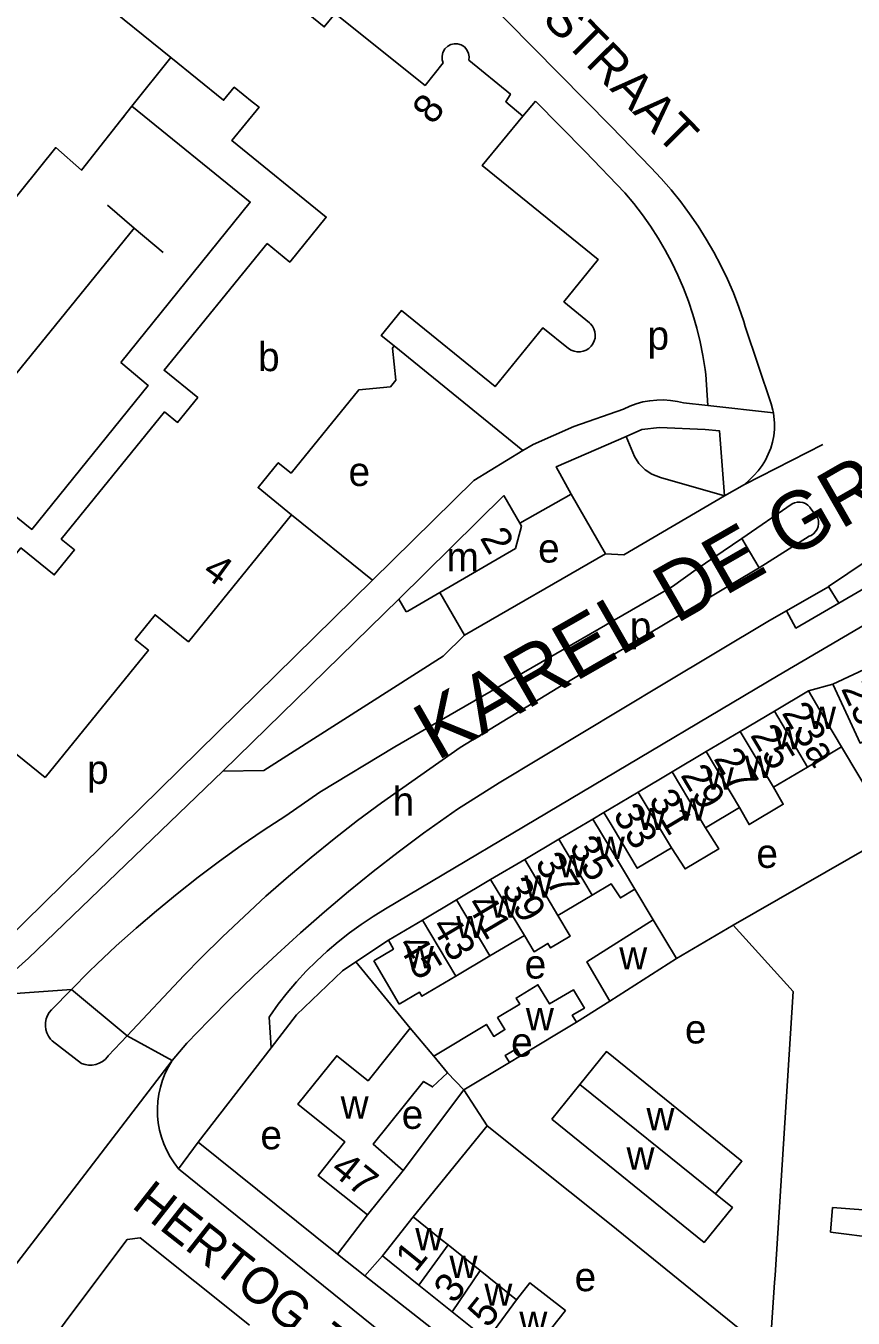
# Model space of a CAD drawing. Extents: x 159700 to 161346, y 381730 to 382922.
# Drawn here: x 160419.2 to 160533.4, y 382582.1 to 382760.5 of the extents above; entities that cross this region are included whole.
import ezdxf

# ---------------------------------------------------------------- set-up
doc = ezdxf.new("R2010")
doc.units = 0
for name, color, linetype in [('BLT_Basislijn', 7, 'Continuous'), ('BLT_Bebouwing', 7, 'Continuous'), ('BLT_Centroide', 7, 'Continuous'), ('BLT_Huisnummer', 7, 'Continuous'), ('BLT_Huisnummer_ tussenligend', 7, 'Continuous'), ('BLT_Onderverdeling_panden', 7, 'Continuous'), ('BLT_Straatnaam', 7, 'Continuous'), ('BLT_Straatnaam_hoofdweg', 7, 'Continuous'), ('BLT_Vlakafsluiter', 7, 'Continuous')]:
    doc.layers.add(name, color=color, linetype=linetype)

msp = doc.modelspace()

# ---------------------------------------------------------------- linework, layer by layer
at = {"layer": 'BLT_Basislijn'}
for p, q in [((160433.88, 382749.39), (160439.23, 382756.14)), ((160487.81, 382748.05), (160489.54, 382750.11)), ((160432.79, 382748.01), (160432.4, 382747.51)), ((160430.48, 382735.74), (160434.18, 382732.58)), ((160394.2, 382683.31), (160434.18, 382732.58)), ((160434.18, 382732.58), (160438.16, 382729.19)), ((160522.09, 382708.31), (160518.51, 382719)), ((160470.04, 382716.3), (160487.83, 382701.85)), ((160513.04, 382712.36), (160513.32, 382708.08)), ((160509.97, 382708.45), (160513.32, 382708.08)), ((160513.32, 382708.08), (160522.38, 382707.07)), ((160501.71, 382707.58), (160494.84, 382705.19)), ((160494.48, 382695.83), (160499.22, 382687.59)), ((160518.38, 382697.17), (160515.63, 382695.63)), ((160524.97, 382694.49), (160518.01, 382689.74)), ((160527.46, 382693.97), (160528.5, 382692.53)), ((160455.9, 382693.01), (160467.05, 382683.96)), ((160518.01, 382689.74), (160520.41, 382685.67)), ((160520.41, 382685.67), (160527.33, 382690.04)), ((160529.99, 382683.09), (160531.4, 382680.79)), ((160476.35, 382682.26), (160479.74, 382676.38)), ((160530.58, 382669.62), (160527.22, 382668.68)), ((160531.8, 382660.96), (160536.7, 382652.73)), ((160478.8, 382652.34), (160474.12, 382649.06)), ((160499.01, 382651.92), (160497.47, 382650.99)), ((160505.79, 382637.1), (160503.26, 382641.3)), ((160509.03, 382631.73), (160516.84, 382636.33)), ((160464.76, 382631.29), (160469.26, 382634.26)), ((160472.26, 382622.14), (160464.76, 382631.29)), ((160427.97, 382629.95), (160425.54, 382627.48)), ((160441.06, 382629.42), (160433.23, 382621.08)), ((160425.54, 382627.48), (160422.77, 382624.66)), ((160425.54, 382627.48), (160433.23, 382621.08)), ((160495.21, 382622.93), (160499.8, 382625.87)), ((160452.79, 382623.66), (160453.08, 382619.43)), ((160433.23, 382621.08), (160430.61, 382618.29)), ((160426.93, 382617.24), (160422.87, 382620.39)), ((160453.08, 382619.43), (160443.02, 382606.37)), ((160485.97, 382617.39), (160487.51, 382618.29)), ((160479.66, 382613.62), (160471.31, 382602.49)), ((160482.89, 382608.65), (160479.66, 382613.62)), ((160482.89, 382608.65), (160472.7, 382596.06)), ((160440.32, 382602.72), (160443.02, 382606.37)), ((160466.4, 382596.34), (160462.26, 382590.93)), ((160466, 382587.92), (160462.26, 382590.93)), ((160466, 382587.92), (160468.44, 382590.7)), ((160521.9, 382577.2), (160522.55, 382587.01))]:
    msp.add_line(p, q, dxfattribs=at)
for points in [[(160505.49, 382740.93), (160500, 382746.62), (160428.28, 382819.33), (160426.69, 382820.38), (160424.21, 382820.93), (160420.96, 382820.92), (160420.04, 382820.56)], [(160392.93, 382705.85), (160423.37, 382743.68), (160426.9, 382740.56), (160433.88, 382749.39)], [(160433.88, 382749.39), (160450.2, 382736.17), (160432.34, 382714)], [(160501.9, 382737.46), (160496.42, 382743.13), (160489.54, 382750.11)], [(160505.49, 382740.93), (160506.92, 382739.41), (160508.29, 382737.84), (160509.59, 382736.22), (160510.83, 382734.54), (160512.01, 382732.82), (160513.12, 382731.06), (160514.16, 382729.25), (160515.13, 382727.41), (160516.03, 382725.53), (160516.86, 382723.62), (160517.62, 382721.67), (160518.29, 382719.7), (160518.51, 382719)], [(160501.9, 382737.46), (160503.14, 382735.97), (160504.31, 382734.43), (160505.43, 382732.84), (160506.47, 382731.2), (160507.45, 382729.53), (160508.36, 382727.82), (160509.2, 382726.06), (160509.96, 382724.28), (160510.65, 382722.47), (160511.27, 382720.63), (160511.81, 382718.76), (160512.27, 382716.88), (160512.65, 382714.98), (160512.95, 382713.06), (160513.04, 382712.36)], [(160390.87, 382673.81), (160393.15, 382674.12), (160397.54, 382670.63), (160416.19, 382694.1), (160420.05, 382690.98), (160436.13, 382710.83), (160432.34, 382714)], [(160501.71, 382707.58), (160502.57, 382707.98), (160503.47, 382708.31), (160504.39, 382708.57), (160505.33, 382708.74), (160506.28, 382708.84), (160507.23, 382708.85), (160508.19, 382708.79), (160509.13, 382708.65), (160509.97, 382708.45)], [(160522.09, 382708.31), (160522.32, 382707.45), (160522.38, 382707.07)], [(160522.38, 382707.07), (160522.46, 382706.57), (160522.53, 382705.68), (160522.52, 382704.79), (160522.43, 382703.91), (160522.26, 382703.03), (160522.01, 382702.18), (160521.68, 382701.35), (160521.29, 382700.55), (160520.82, 382699.79), (160520.29, 382699.07), (160519.69, 382698.41), (160519.04, 382697.8), (160518.38, 382697.17)], [(160494.84, 382705.19), (160489.24, 382702.71), (160487.83, 382701.85)], [(160502.06, 382703.81), (160504.23, 382704.75), (160506.67, 382705.06), (160512.96, 382704.75), (160514.93, 382704.59), (160515.63, 382695.63)], [(160494.48, 382695.83), (160492.42, 382699.63), (160502.06, 382703.81)], [(160515.63, 382695.63), (160506.82, 382698.15), (160505.6, 382698.61), (160504.71, 382699.21), (160503.82, 382700.1), (160503.2, 382701.04), (160502.06, 382703.81)], [(160487.83, 382701.85), (160481.07, 382697.74), (160467.05, 382683.96)], [(160529.99, 382683.09), (160548.53, 382695.55), (160552.09, 382697.77)], [(160494.48, 382695.83), (160487.4, 382691.84)], [(160515.63, 382695.63), (160501.75, 382687.49), (160499.22, 382687.59)], [(160524.97, 382694.49), (160525.32, 382694.66), (160525.69, 382694.75), (160526.07, 382694.76), (160526.45, 382694.7), (160526.81, 382694.55), (160527.12, 382694.34), (160527.39, 382694.06), (160527.46, 382693.97)], [(160531.4, 382680.79), (160541.2, 382686.51), (160551.14, 382692.14), (160554.4, 382693.75)], [(160528.5, 382692.53), (160528.6, 382692.15), (160528.61, 382691.75), (160528.55, 382691.36), (160528.41, 382691), (160528.19, 382690.67), (160527.92, 382690.38), (160527.59, 382690.16), (160527.33, 382690.04)], [(160518.01, 382689.74), (160511.75, 382685.46), (160508.48, 382683.1), (160475.37, 382663.99), (160470.14, 382660.98), (160459.8, 382654.69), (160455.09, 382651.42)], [(160555.31, 382689.89), (160546.62, 382684.68), (160523.06, 382670.8), (160468.88, 382638.59)], [(160479.74, 382676.38), (160499.22, 382687.59)], [(160468.31, 382653.25), (160479.17, 382660.85), (160492.65, 382669.09), (160519.87, 382685.33), (160520.41, 382685.67)], [(160467.05, 382683.96), (160419.05, 382636.78), (160417.13, 382634.83)], [(160524.19, 382679.74), (160529.88, 382683.01), (160529.99, 382683.09)], [(160470.7, 382681.36), (160446.43, 382657.59)], [(160507.17, 382669.62), (160521.83, 382678.39), (160524.19, 382679.74)], [(160524.19, 382679.74), (160525.49, 382677.35), (160531.4, 382680.79)], [(160446.43, 382657.59), (160452.08, 382657.71), (160476.8, 382673.46), (160479.74, 382676.38)], [(160507.17, 382669.62), (160484.56, 382656), (160478.8, 382652.34)], [(160446.43, 382657.59), (160419.61, 382631.81), (160413.81, 382626.64)], [(160468.31, 382653.25), (160465.02, 382650.79), (160461.78, 382648.27), (160458.59, 382645.68), (160455.46, 382643.04), (160452.37, 382640.33), (160449.34, 382637.56), (160446.36, 382634.74), (160443.44, 382631.85), (160441.06, 382629.42)], [(160516.84, 382636.33), (160539.04, 382649.09), (160536.7, 382652.73)], [(160455.09, 382651.42), (160452, 382649.4), (160448.96, 382647.32), (160445.96, 382645.17), (160443.01, 382642.95), (160440.11, 382640.67), (160437.25, 382638.33), (160434.45, 382635.93), (160431.71, 382633.47), (160429.01, 382630.95), (160427.97, 382629.95)], [(160474.12, 382649.06), (160470.62, 382646.43), (160467.17, 382643.74), (160463.77, 382640.99), (160460.43, 382638.17), (160457.13, 382635.3), (160453.89, 382632.36), (160450.7, 382629.36), (160447.57, 382626.31), (160444.49, 382623.2), (160441.47, 382620.04), (160439.42, 382617.66)], [(160468.88, 382638.59), (160467.18, 382637.55), (160465.51, 382636.45), (160463.89, 382635.28), (160462.32, 382634.05), (160460.8, 382632.75), (160459.34, 382631.39), (160457.93, 382629.98), (160456.57, 382628.51), (160455.28, 382626.99), (160454.05, 382625.42), (160452.88, 382623.8), (160452.79, 382623.66)], [(160516.84, 382636.33), (160525.13, 382627.17), (160522.63, 382588.01), (160522.55, 382587.01)], [(160464.76, 382631.29), (160462.91, 382630.06), (160456.58, 382623.97), (160453.08, 382619.43)], [(160422.77, 382624.66), (160422.46, 382624.28), (160422.22, 382623.85), (160422.05, 382623.39), (160421.95, 382622.91), (160421.94, 382622.42), (160422, 382621.93), (160422.15, 382621.46), (160422.36, 382621.02), (160422.65, 382620.62), (160422.87, 382620.39)], [(160426.93, 382617.24), (160427.4, 382617.09), (160427.89, 382617.02), (160428.39, 382617.03), (160428.88, 382617.11), (160429.35, 382617.28), (160429.79, 382617.51), (160430.18, 382617.81), (160430.52, 382618.18), (160430.61, 382618.29)], [(160440.32, 382602.72), (160439.71, 382603.51), (160439.16, 382604.35), (160438.68, 382605.23), (160438.27, 382606.15), (160437.94, 382607.09), (160437.69, 382608.06), (160437.51, 382609.04), (160437.41, 382610.04), (160437.39, 382611.04), (160437.45, 382612.04), (160437.59, 382613.03), (160437.81, 382614), (160438.11, 382614.96), (160438.48, 382615.89), (160438.93, 382616.79), (160439.42, 382617.66)], [(160482.89, 382608.65), (160500, 382594.99), (160521.9, 382577.2)], [(160462.26, 382590.93), (160461.96, 382591.17), (160443.02, 382606.37)], [(160491.46, 382544.8), (160497.56, 382552.05), (160497.99, 382554.89), (160497.77, 382555.53), (160491.25, 382561.57), (160440.32, 382602.72)], [(160425.28, 382599.18), (160384.45, 382546.02), (160383.14, 382544.19), (160379.74, 382536.86), (160366.91, 382518.26), (160360.11, 382511.98), (160356.18, 382508.31), (160321.11, 382459.87)], [(160450.08, 382581.13), (160435.03, 382593.18), (160433.21, 382592.93), (160424.89, 382581.85), (160387.63, 382530.18), (160388, 382528.33), (160391.85, 382526)], [(160506.02, 382557.47), (160500, 382561.24), (160466, 382587.92)]]:
    msp.add_lwpolyline(points, dxfattribs=at)
at = {"layer": 'BLT_Bebouwing'}
for p, q in [((160485.19, 382695.64), (160487.4, 382691.84)), ((160487.65, 382691.41), (160486.81, 382688.34)), ((160487.4, 382691.84), (160487.65, 382691.41)), ((160486.81, 382688.34), (160476.35, 382682.26)), ((160471.73, 382679.61), (160470.7, 382681.36)), ((160476.35, 382682.26), (160471.96, 382679.7)), ((160471.96, 382679.7), (160471.73, 382679.61)), ((160535.62, 382671.95), (160530.58, 382669.62)), ((160522.52, 382665.89), (160527.22, 382668.68)), ((160517.82, 382663.09), (160522.52, 382665.89)), ((160513.12, 382660.3), (160517.82, 382663.09)), ((160508.43, 382657.51), (160513.12, 382660.3)), ((160531.8, 382660.96), (160527.11, 382658.17)), ((160527.11, 382658.17), (160522.41, 382655.38)), ((160503.73, 382654.72), (160508.43, 382657.51)), ((160517.71, 382652.59), (160513.01, 382649.8)), ((160492.77, 382648.21), (160488.07, 382645.42)), ((160488.07, 382645.42), (160483.37, 382642.63)), ((160483.37, 382642.63), (160478.66, 382639.84)), ((160497.36, 382640.47), (160492.66, 382637.68)), ((160478.66, 382639.84), (160473.96, 382637.05)), ((160473.96, 382637.05), (160469.26, 382634.26)), ((160488.02, 382634.92), (160483.26, 382632.09)), ((160483.26, 382632.09), (160478.56, 382629.3)), ((160495.21, 382622.93), (160487.51, 382618.29)), ((160472.26, 382622.14), (160475.51, 382618.24)), ((160475.51, 382618.24), (160477.43, 382615.94)), ((160485.97, 382617.39), (160479.66, 382613.62)), ((160495.69, 382614.36), (160491.82, 382609.55)), ((160471.31, 382602.49), (160466.4, 382596.34)), ((160468.44, 382590.7), (160472.7, 382596.06)), ((160477.5, 382592.2), (160481.91, 382588.65)), ((160473.46, 382586.66), (160468.44, 382590.7)), ((160481.91, 382588.65), (160486.92, 382584.62)), ((160478.08, 382582.95), (160473.46, 382586.66)), ((160482.88, 382579.09), (160478.08, 382582.95))]:
    msp.add_line(p, q, dxfattribs=at)
for points in [[(160471.4, 382754.61), (160461.91, 382762.21), (160460.41, 382760.36), (160456.95, 382763.17), (160460.66, 382767.73)], [(160428.99, 382764.45), (160439.23, 382756.14)], [(160476.84, 382755.38), (160476.7, 382755.81), (160476.68, 382756.32), (160476.79, 382756.84), (160477.06, 382757.31), (160477.45, 382757.68), (160477.89, 382757.92), (160478.34, 382758.02), (160478.8, 382758.02), (160479.28, 382757.88), (160479.74, 382757.6), (160480.1, 382757.19), (160480.33, 382756.7), (160480.41, 382756.21), (160480.36, 382755.75)], [(160439.23, 382756.14), (160446.52, 382750.22), (160447.98, 382752.03), (160450.48, 382750), (160451.41, 382749.25), (160447.68, 382744.66), (160460.69, 382734.09), (160455.66, 382727.89), (160452.52, 382730.44)], [(160476.84, 382755.38), (160474.32, 382752.27), (160471.4, 382754.61)], [(160487.81, 382748.05), (160485.45, 382750.02), (160486.09, 382751.07), (160480.36, 382755.75)], [(160497.01, 382719.52), (160493.47, 382722.4), (160498.21, 382728.23), (160482.22, 382741.21), (160487.81, 382748.05)], [(160404.37, 382670.95), (160418.56, 382688.43), (160423.15, 382684.7), (160425.96, 382688.15), (160424.12, 382689.64), (160438.38, 382707.2), (160440.17, 382705.75), (160442.95, 382709.18), (160438.31, 382712.94), (160452.52, 382730.44)], [(160494.12, 382715.95), (160490.59, 382718.82), (160483.99, 382710.7), (160471.05, 382721.2), (160468.25, 382717.76), (160470.04, 382716.3)], [(160494.12, 382715.95), (160494.48, 382715.72), (160494.88, 382715.57), (160495.3, 382715.49), (160495.73, 382715.49), (160496.15, 382715.58), (160496.55, 382715.73), (160496.91, 382715.96), (160497.23, 382716.26), (160497.48, 382716.6), (160497.66, 382716.99), (160497.77, 382717.4), (160497.8, 382717.83), (160497.75, 382718.26), (160497.63, 382718.66), (160497.43, 382719.04), (160497.16, 382719.38), (160497.01, 382719.52)], [(160470.04, 382716.3), (160469.81, 382716.02), (160470.27, 382711.59), (160469.53, 382710.68), (160465.16, 382710.23), (160455.84, 382698.75), (160454.07, 382700.19), (160451.29, 382696.76), (160455.9, 382693.01)], [(160470.7, 382681.36), (160485.19, 382695.64)], [(160455.9, 382693.01), (160441.66, 382675.48), (160437.07, 382679.2), (160434.3, 382675.8), (160436.15, 382674.3), (160421.88, 382656.73)], [(160530.58, 382669.62), (160532.68, 382665.08), (160534.35, 382661.48), (160539.39, 382663.82)], [(160527.22, 382668.68), (160529.77, 382664.38), (160531.8, 382660.96)], [(160421.88, 382656.73), (160416.09, 382661.44), (160413.25, 382657.92)], [(160503.73, 382654.72), (160500, 382652.51), (160499.01, 382651.92)], [(160522.41, 382655.38), (160523.75, 382653.03), (160519.04, 382650.23), (160517.71, 382652.59)], [(160497.47, 382650.99), (160492.77, 382648.21)], [(160503.26, 382641.3), (160500, 382646.77), (160497.47, 382650.99)], [(160499.01, 382651.92), (160500, 382650.26), (160501.57, 382647.62), (160503.61, 382644.21), (160508.31, 382647)], [(160513.01, 382649.8), (160514.84, 382646.87), (160510.19, 382644.11), (160508.31, 382647)], [(160503.26, 382641.3), (160501.27, 382640.11), (160500, 382642.04), (160497.36, 382640.47)], [(160492.66, 382637.68), (160494.35, 382634.84), (160491.64, 382633.2), (160491.27, 382633.83), (160489.37, 382632.68), (160488.02, 382634.92)], [(160499.8, 382625.87), (160496.62, 382631.27), (160505.79, 382637.1)], [(160505.79, 382637.1), (160509.03, 382631.73)], [(160469.26, 382634.26), (160469.96, 382633.04), (160467.23, 382631.42)], [(160467.23, 382631.42), (160470.74, 382625.45)], [(160509.03, 382631.73), (160499.8, 382625.87)], [(160470.74, 382625.45), (160473.54, 382627.1), (160473.88, 382626.52), (160478.56, 382629.3)], [(160475.51, 382618.24), (160482.79, 382622.64), (160483.79, 382620.99), (160485.33, 382621.92), (160484.33, 382623.58), (160487.38, 382625.42), (160486.87, 382626.27), (160489.9, 382628.11), (160491.5, 382625.47), (160494.78, 382627.42), (160496.31, 382624.89), (160494.64, 382623.9), (160495.21, 382622.93)], [(160466.4, 382596.34), (160459.57, 382601.8), (160463.26, 382606.42), (160456.77, 382611.61), (160462.14, 382618.32), (160466.45, 382614.87), (160472.26, 382622.14)], [(160487.51, 382618.29), (160486.93, 382619.26), (160485.38, 382618.37), (160485.97, 382617.39)], [(160514.4, 382599.25), (160518.04, 382603.75), (160499.35, 382618.88), (160495.69, 382614.36)], [(160477.43, 382615.94), (160475.35, 382614.02), (160474.12, 382614.77), (160467.18, 382606.1), (160471.31, 382602.49)], [(160479.66, 382613.62), (160477.43, 382615.94)], [(160491.82, 382609.55), (160512.83, 382592.54), (160516.74, 382597.36), (160514.4, 382599.25)], [(160554.26, 382595.52), (160545.63, 382596.02), (160537.49, 382601.11), (160537.15, 382596.84), (160530.56, 382597.35), (160530.28, 382593.98), (160536.85, 382593.15), (160536.84, 382592.96), (160544.03, 382592.06)], [(160472.7, 382596.06), (160476.55, 382592.96), (160477.5, 382592.2)], [(160486.92, 382584.62), (160488.8, 382586.98), (160493.69, 382583.14), (160491.77, 382580.72)]]:
    msp.add_lwpolyline(points, dxfattribs=at)
at = {"layer": 'BLT_Onderverdeling_panden'}
for p, q in [((160527.11, 382658.17), (160522.52, 382665.89)), ((160522.41, 382655.38), (160517.82, 382663.09)), ((160517.71, 382652.59), (160513.12, 382660.3)), ((160513.01, 382649.8), (160508.43, 382657.51)), ((160508.31, 382647), (160503.73, 382654.72)), ((160497.36, 382640.47), (160492.77, 382648.21)), ((160492.66, 382637.68), (160488.07, 382645.42)), ((160488.02, 382634.92), (160483.37, 382642.63)), ((160483.26, 382632.09), (160478.66, 382639.84)), ((160478.56, 382629.3), (160473.96, 382637.05)), ((160495.69, 382614.36), (160514.4, 382599.25)), ((160473.46, 382586.66), (160477.5, 382592.2)), ((160478.08, 382582.95), (160481.91, 382588.65)), ((160482.88, 382579.09), (160486.92, 382584.62))]:
    msp.add_line(p, q, dxfattribs=at)
at = {"layer": 'BLT_Vlakafsluiter'}
for p, q in [((160529.19, 382702.71), (160518.38, 382697.17)), ((160413.81, 382626.64), (160425.54, 382627.48)), ((160433.23, 382621.08), (160439.42, 382617.66)), ((160425.28, 382599.18), (160439.42, 382617.66))]:
    msp.add_line(p, q, dxfattribs=at)

# ---------------------------------------------------------------- texts
at = {"layer": 'BLT_Centroide'}
for s, p in [('p', (160505.02, 382715.78)), ('b', (160451.28, 382712.83)), ('e', (160463.76, 382696.97)), ('e', (160489.92, 382686.4)), ('m', (160477.28, 382685.19)), ('p', (160502.58, 382675.61)), ('w', (160527.16, 382663.44)), ('w', (160522.47, 382660.62)), ('p', (160427.69, 382655.85)), ('w', (160513.06, 382655.06)), ('w', (160518.44, 382656.67)), ('h', (160469.84, 382651.45)), ('w', (160509.28, 382650.78)), ('w', (160503.66, 382649.47)), ('w', (160498.02, 382645.48)), ('e', (160520.04, 382644.25)), ('w', (160492.72, 382642.95)), ('w', (160488.02, 382640.14)), ('w', (160483.31, 382637.36)), ('w', (160478.61, 382634.56)), ('w', (160471.67, 382630.38)), ('w', (160501.11, 382630.23)), ('e', (160488.07, 382628.97)), ('w', (160488.23, 382621.82)), ('e', (160510.18, 382620.01)), ('e', (160486.19, 382618.2)), ('w', (160462.67, 382609.65)), ('e', (160471.1, 382608.22)), ('w', (160504.87, 382608.02)), ('e', (160451.6, 382605.4)), ('w', (160502.12, 382602.59)), ('w', (160472.97, 382591.45)), ('w', (160477.69, 382587.64)), ('e', (160494.96, 382585.81)), ('w', (160482.5, 382583.8)), ('w', (160487.33, 382579.91))]:
    msp.add_text(s, height=4, dxfattribs=at).set_placement(p)
at = {"layer": 'BLT_Huisnummer'}
for s, rotation, p in [('8', 51.3883, (160475.38, 382746.7)), ('2', 299.9819, (160481.82, 382689.81)), ('4', 323.9819, (160443.41, 382684.74)), ('23', 294.8659, (160531.67, 382669)), ('23a', 300.7152, (160523.46, 382665.65)), ('25', 300.7152, (160519.11, 382662.57)), ('29', 300.7152, (160509.49, 382657.05)), ('33', 300.8548, (160500.17, 382651.63)), ('37', 300.6689, (160489.4, 382644.93)), ('41', 300.6703, (160479.95, 382639.24)), ('45', 300.8694, (160470.43, 382633.63)), ('47', 321.3453, (160461.09, 382602.26)), ('1', 51.2081, (160473.01, 382588.27)), ('5', 51.2106, (160482.99, 382580.59))]:
    msp.add_text(s, height=4, rotation=rotation, dxfattribs=at).set_placement(p)
at = {"layer": 'BLT_Huisnummer_ tussenligend'}
for s, rotation, p in [('27', 300.7152, (160514.06, 382659.35)), ('31', 300.7152, (160505.08, 382653.63)), ('35', 300.8548, (160494.12, 382647.18)), ('39', 300.6689, (160484.76, 382641.49)), ('43', 300.6703, (160475.08, 382636.2)), ('3', 51.2081, (160478.3, 382583.94))]:
    msp.add_text(s, height=4, rotation=rotation, dxfattribs=at).set_placement(p)
at = {"layer": 'BLT_Straatnaam'}
for s, rotation, p in [('ANNA VAN ENGELANDSTRAAT', 314.6085, (160439.18, 382813.12)), ('HERTOG JAN I LAAN', 321.834, (160433.68, 382597.47))]:
    msp.add_text(s, height=5, rotation=rotation, dxfattribs=at).set_placement(p)
at = {"layer": 'BLT_Straatnaam_hoofdweg'}
msp.add_text('KAREL DE GROTELAAN', height=8, rotation=29.8553, dxfattribs=at).set_placement((160475.95, 382658.93))

doc.saveas('drawing.dxf')
